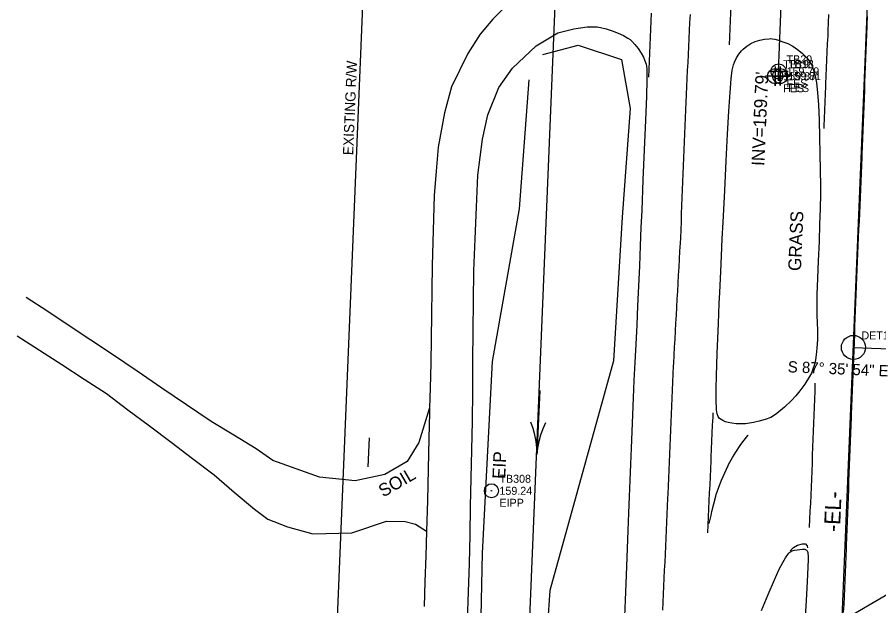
# Model space of a CAD drawing. Extents: x 2262665 to 2270527, y 505476 to 514960.
# Drawn here: x 2266110 to 2266379, y 511484.8 to 511668.5 of the extents above; entities that cross this region are included whole.
import ezdxf

# ---------------------------------------------------------------- set-up
doc = ezdxf.new("R2010")
doc.units = 0
for name, color, linetype in [('Default Symbol Cogo Number', 7, 'Continuous'), ('Exist Horizontal Alignment', 7, 'Continuous'), ('Exist Horizontal Alignment Direction Label', 7, 'Continuous'), ('Exist Hydro River Flow Arrow CELL', 7, 'Continuous'), ('Exist Hydro Stream or Body of Water', 7, 'Continuous'), ('Exist Other Culture Sign', 7, 'Continuous'), ('Exist Property Iron Pin CELL', 7, 'Continuous'), ('Exist Property Iron Pin Cogo Comment', 7, 'Continuous'), ('Exist Property Iron Pin Cogo Elevation', 7, 'Continuous'), ('Exist Property Iron Pin Cogo Number', 7, 'Continuous'), ('Exist Property Iron Pin Text', 7, 'Continuous'), ('Exist Right of Way Control of Access Line', 7, 'Continuous'), ('Exist Right of Way Line', 7, 'Continuous'), ('Exist Right of Way Line Text', 7, 'Continuous'), ('Exist Roads EOP', 7, 'Continuous'), ('Exist Roads EOT', 7, 'Continuous'), ('Exist Roads Soil', 7, 'Continuous'), ('Exist Roads Soil Text', 7, 'Continuous'), ('Exist Structure Minor Paved Ditch or Gutter Cogo Comment', 7, 'Continuous'), ('Exist Structure Minor Paved Ditch or Gutter Cogo Elevation', 7, 'Continuous'), ('Exist Structure Minor Paved Ditch or Gutter Cogo Number', 7, 'Continuous'), ('Exist Structure Minor Paved Ditch or Gutter Cogo Point CELL', 7, 'Continuous'), ('Exist Structure Minor Pipes RCP 15 Inch', 7, 'Continuous'), ('Exist Structure Minor Pipes RCP 15 Inch Cogo Comment', 7, 'Continuous'), ('Exist Structure Minor Pipes RCP 15 Inch Cogo Elevation', 7, 'Continuous'), ('Exist Structure Minor Pipes RCP 15 Inch Cogo Number', 7, 'Continuous'), ('Exist Structure Minor Pipes RCP 15 Inch Cogo Point CELL', 7, 'Continuous'), ('Exist Structure Minor Pipes RCP 15 Inch Invert', 7, 'Continuous'), ('Exist Vegetation Hedge Row Text', 7, 'Continuous')]:
    doc.layers.add(name, color=color, linetype=linetype)

msp = doc.modelspace()

# ---------------------------------------------------------------- linework, layer by layer
at = {"layer": 'Exist Horizontal Alignment'}
for p, q in [((2266320.5, 510340.11), (2266385.32, 511909.14)), ((2266371.12, 511565.48), (2266394.22, 511564.51))]:
    msp.add_line(p, q, dxfattribs=at)
msp.add_circle((2266371.12, 511565.48), 3.75, dxfattribs=at)
at = {"layer": 'Exist Hydro River Flow Arrow CELL'}
msp.add_line((2266272.72, 511542.01), (2266272.72, 511542.01), dxfattribs=at)
msp.add_lwpolyline([(2266275.01, 511541.91), (2266274.14, 511540.05), (2266273.41, 511538.11), (2266272.85, 511536.09), (2266272.45, 511534.06), (2266272.28, 511532.02), (2266273.16, 511552), (2266272.28, 511532.02), (2266272.3, 511534.07), (2266272.08, 511536.13), (2266271.69, 511538.19), (2266271.14, 511540.19), (2266270.44, 511542.11)], dxfattribs=at)
at = {"layer": 'Exist Hydro Stream or Body of Water'}
for points in [[(2266274.13, 511656.9), (2266285.13, 511659.83), (2266298.69, 511655.35), (2266301.39, 511640.07), (2266298.87, 511606.11), (2266296.18, 511561.33), (2266276.32, 511489.55), (2266273.39, 511447.18), (2266269.15, 511402.44), (2266266.62, 511350.29), (2266263.29, 511284.61), (2266261.41, 511233.5)], [(2266242.57, 511233.58), (2266245.62, 511286.27), (2266249.21, 511350.34), (2266253.36, 511402.9), (2266254.17, 511446.9), (2266255.33, 511501.23), (2266258.4, 511561.12), (2266266.85, 511608.7), (2266269.9, 511649.03)]]:
    msp.add_lwpolyline(points, dxfattribs=at)
at = {"layer": 'Exist Other Culture Sign'}
msp.add_line((2266219.93, 511537.26), (2266219.52, 511528.24), dxfattribs=at)
at = {"layer": 'Exist Property Iron Pin CELL'}
for radius in [2.2, 0.0707]:
    msp.add_circle((2266258.09, 511520.72), radius, dxfattribs=at)
at = {"layer": 'Exist Right of Way Control of Access Line'}
msp.add_line((2266232.79, 510577.78), (2266283.35, 511801.46), dxfattribs=at)
at = {"layer": 'Exist Right of Way Line'}
msp.add_line((2266169.17, 510491.24), (2266223.4, 511803.97), dxfattribs=at)
at = {"layer": 'Exist Roads EOP'}
for points in [[(2266263.53, 511672.95), (2266258.49, 511667.96), (2266254.61, 511663.28), (2266250.67, 511657.18), (2266245.65, 511646.8), (2266243.39, 511638.75), (2266241.41, 511628.01), (2266240.83, 511620.47), (2266240.24, 511612.93), (2266240.03, 511605.63), (2266239.82, 511598.33), (2266239.6, 511591.03), (2266239.48, 511583.41), (2266239.36, 511575.79), (2266239.24, 511568.17), (2266239.12, 511560.55), (2266238.92, 511552.76), (2266238.77, 511546.65), (2266238.72, 511544.97), (2266238.52, 511537.18), (2266238.33, 511527.42), (2266238.14, 511517.65), (2266237.84, 511508.13), (2266237.58, 511500.29), (2266237.33, 511492.45), (2266237.08, 511484.6)], [(2266250.58, 511480.2), (2266250.91, 511489.13), (2266251.23, 511498.06), (2266251.41, 511506.94), (2266251.59, 511515.81), (2266251.77, 511524.68), (2266251.95, 511533.55), (2266252.13, 511542.43), (2266252.23, 511551.82), (2266252.33, 511561.22), (2266252.43, 511570.61), (2266252.53, 511580.01), (2266252.63, 511589.41), (2266253.04, 511599.34), (2266253.46, 511609.28), (2266253.87, 511619.22), (2266255.31, 511630.53), (2266256.96, 511638.05), (2266260.43, 511646.66), (2266264.7, 511652.69), (2266272.01, 511659.6), (2266278.87, 511663.67), (2266283.84, 511664.88), (2266287.98, 511665.5), (2266290.81, 511665.58)], [(2266290.81, 511665.58), (2266291.06, 511665.55), (2266292.13, 511665.33), (2266293.89, 511664.89), (2266295.75, 511664.32), (2266297.61, 511663.62), (2266299.28, 511662.86), (2266300.73, 511662.02), (2266301.36, 511661.57), (2266301.92, 511661.1), (2266302.89, 511660.06), (2266303.87, 511658.79), (2266304.85, 511657.34), (2266305.57, 511656.06), (2266306.02, 511654.97), (2266306.37, 511653.85), (2266306.52, 511653.26), (2266306.63, 511652.4), (2266306.66, 511649.15), (2266306.46, 511643.83), (2266306.16, 511636.43), (2266305.78, 511627.2), (2266305.4, 511617.8), (2266305.01, 511608.25), (2266304.79, 511602.93), (2266304.55, 511597.17), (2266304.29, 511590.98), (2266304.02, 511584.64), (2266303.74, 511578.45), (2266303.45, 511572.41), (2266303.15, 511566.52), (2266302.85, 511560.78), (2266302.58, 511555.18), (2266302.33, 511549.72), (2266302.1, 511544.4), (2266301.88, 511539.19), (2266301.68, 511534.05), (2266301.48, 511528.98), (2266301.29, 511523.98), (2266301.1, 511518.93), (2266300.91, 511513.7), (2266300.7, 511508.29), (2266300.47, 511502.7), (2266300.25, 511497.12), (2266300.03, 511491.75), (2266299.83, 511486.58), (2266299.43, 511476.6)], [(2266342.42, 511483.31), (2266344.51, 511488.3), (2266346.45, 511492.93), (2266347.97, 511496.3), (2266349.08, 511498.37), (2266349.94, 511499.84), (2266350.6, 511500.84), (2266350.93, 511501.22), (2266351.27, 511501.53), (2266351.61, 511501.77), (2266351.96, 511501.95), (2266352.32, 511502.09), (2266352.71, 511502.19), (2266353.51, 511502.31), (2266354.36, 511502.4), (2266355.21, 511502.49), (2266355.81, 511502.5), (2266356, 511502.47), (2266356.15, 511502.42), (2266356.3, 511502.34), (2266356.44, 511502.24), (2266356.58, 511502.11), (2266356.7, 511501.95), (2266356.8, 511501.74), (2266356.88, 511501.49), (2266356.93, 511501.19), (2266356.98, 511500.39), (2266356.97, 511499.27), (2266356.87, 511496.93), (2266356.67, 511492.45), (2266356.37, 511486.48), (2266355.99, 511479.65)]]:
    msp.add_lwpolyline(points, dxfattribs=at)
msp.add_lwpolyline([(2266359.86, 511571.16), (2266359.88, 511567.91), (2266359.7, 511565.28), (2266359.45, 511563.21), (2266359.24, 511561.61), (2266358.94, 511560.12), (2266358.39, 511558.37), (2266357.99, 511557.4), (2266357.45, 511556.35), (2266355.95, 511554.05), (2266354.36, 511551.91), (2266353.17, 511550.38), (2266351.77, 511548.87), (2266349.58, 511546.78), (2266347.21, 511544.8), (2266346.2, 511544.12), (2266345.29, 511543.64), (2266343.53, 511542.96), (2266341.65, 511542.41), (2266339.93, 511542.02), (2266338.65, 511541.78), (2266337.46, 511541.65), (2266336, 511541.62), (2266334.51, 511541.67), (2266333.18, 511541.81), (2266332.05, 511542.01), (2266331.15, 511542.25), (2266330.74, 511542.42), (2266330.3, 511542.66), (2266329.32, 511543.33), (2266328.86, 511543.9), (2266328.53, 511544.78), (2266328.34, 511545.97), (2266328.29, 511549.17), (2266328.31, 511552.64), (2266328.36, 511556.64), (2266328.57, 511563.56), (2266328.94, 511572.9), (2266329.2, 511579.22), (2266329.37, 511582.64), (2266329.69, 511589.22), (2266329.92, 511594.07), (2266330.17, 511599.38), (2266330.42, 511604.55), (2266330.92, 511614.5), (2266331.39, 511623.73), (2266331.83, 511632.07), (2266332.24, 511639.26), (2266332.6, 511645.02), (2266332.95, 511649.29), (2266333.3, 511651.98), (2266333.72, 511653.73), (2266333.97, 511654.5), (2266334.59, 511655.84), (2266335.33, 511657.03), (2266335.74, 511657.58), (2266336.19, 511658.1), (2266336.69, 511658.6), (2266337.85, 511659.52), (2266339.13, 511660.31), (2266340.46, 511660.93), (2266341.87, 511661.39), (2266343.4, 511661.69), (2266344.78, 511661.84), (2266345.31, 511661.86), (2266345.72, 511661.83), (2266346.58, 511661.67), (2266347.72, 511661.37), (2266349.07, 511660.92), (2266350.59, 511660.3), (2266352.17, 511659.49), (2266353.69, 511658.47), (2266355.13, 511657.3), (2266356.43, 511656), (2266357, 511655.32), (2266357.5, 511654.64), (2266357.91, 511653.94), (2266358.24, 511653.24), (2266358.77, 511651.76), (2266359.21, 511650.13), (2266359.58, 511648.02), (2266359.91, 511645.05), (2266360.18, 511641.19), (2266360.38, 511636.39), (2266360.53, 511631.14), (2266360.66, 511625.93), (2266360.76, 511620.82), (2266360.8, 511615.88), (2266360.8, 511613.46), (2266360.73, 511608.7), (2266360.58, 511603.93), (2266360.38, 511598.52), (2266360.15, 511592.54), (2266359.92, 511587), (2266359.73, 511582.15), (2266359.66, 511578.48), (2266359.71, 511575.85), (2266359.8, 511572.87)], close=True, dxfattribs=at)
at = {"layer": 'Exist Roads EOT'}
for points in [[(2266332.38, 511659.92), (2266332.49, 511662.42), (2266332.61, 511664.92), (2266332.73, 511667.41), (2266332.85, 511669.91), (2266332.96, 511672.41), (2266333.08, 511674.9), (2266333.2, 511677.4), (2266333.31, 511679.9), (2266333.43, 511682.4), (2266333.55, 511684.89), (2266333.67, 511687.39), (2266333.78, 511689.89), (2266333.85, 511691.33), (2266333.97, 511693.83), (2266334.1, 511696.32), (2266334.22, 511698.82), (2266334.34, 511701.32), (2266334.39, 511702.34)], [(2266307.22, 511649.82), (2266307.33, 511652.32), (2266307.44, 511654.82), (2266307.56, 511657.31), (2266307.67, 511659.81), (2266307.78, 511662.31), (2266307.89, 511664.81), (2266308, 511667.3), (2266308.12, 511669.8)], [(2266311.6, 511483.45), (2266311.72, 511485.95), (2266311.83, 511488.45), (2266311.95, 511490.95), (2266312.06, 511493.44), (2266312.18, 511495.94), (2266312.3, 511498.44), (2266312.41, 511500.94), (2266312.53, 511503.43), (2266312.64, 511505.93), (2266312.76, 511508.43), (2266312.88, 511510.92), (2266312.99, 511513.42), (2266313.11, 511515.92), (2266313.22, 511518.42), (2266313.28, 511519.63), (2266313.39, 511522.13), (2266313.49, 511524.63), (2266313.6, 511527.12), (2266313.7, 511529.62), (2266313.81, 511532.12), (2266313.91, 511534.62), (2266314.02, 511537.12), (2266314.13, 511539.61), (2266314.23, 511542.11), (2266314.34, 511544.61), (2266314.44, 511547.11), (2266314.55, 511549.6), (2266314.66, 511552.1), (2266314.76, 511554.6), (2266314.87, 511557.1), (2266314.97, 511559.6), (2266315.02, 511560.6), (2266315.15, 511563.1), (2266315.29, 511565.59), (2266315.43, 511568.09), (2266315.57, 511570.59), (2266315.71, 511573.08), (2266315.85, 511575.58), (2266315.99, 511578.08), (2266316.13, 511580.57), (2266316.26, 511583.07), (2266316.4, 511585.56), (2266316.54, 511588.06), (2266316.68, 511590.56), (2266316.82, 511593.05), (2266316.96, 511595.55), (2266317.1, 511598.04), (2266317.19, 511599.65), (2266317.29, 511602.15), (2266317.39, 511604.65), (2266317.49, 511607.14), (2266317.59, 511609.64), (2266317.68, 511612.14), (2266317.78, 511614.64), (2266317.88, 511617.14), (2266317.98, 511619.63), (2266318.08, 511622.13), (2266318.18, 511624.63), (2266318.28, 511627.13), (2266318.38, 511629.63), (2266318.48, 511632.12), (2266318.58, 511634.62), (2266318.68, 511637.12), (2266318.78, 511639.62), (2266318.87, 511641.98), (2266318.99, 511644.48), (2266319.12, 511646.97), (2266319.24, 511649.47), (2266319.36, 511651.97), (2266319.48, 511654.46), (2266319.6, 511656.96), (2266319.72, 511659.46), (2266319.84, 511661.95), (2266319.96, 511664.45), (2266320.08, 511666.95), (2266320.2, 511669.45)], [(2266363.32, 511669.36), (2266363.24, 511666.86), (2266363.15, 511664.36), (2266363.09, 511662.75), (2266362.97, 511660.25), (2266362.86, 511657.75), (2266362.75, 511655.25), (2266362.63, 511652.76), (2266362.52, 511650.26), (2266362.4, 511647.76), (2266362.37, 511647.02), (2266362.27, 511644.52), (2266362.17, 511642.02), (2266362.07, 511639.52), (2266361.97, 511637.02), (2266361.87, 511634.53), (2266361.84, 511633.79)], [(2266375.46, 511668.82), (2266375.35, 511666.32), (2266375.32, 511665.7), (2266375.22, 511663.2), (2266375.12, 511660.7), (2266375.02, 511658.21), (2266374.93, 511655.71), (2266374.83, 511653.21), (2266374.73, 511650.71), (2266374.63, 511648.21), (2266374.53, 511645.72), (2266374.44, 511643.22), (2266374.34, 511640.72), (2266374.24, 511638.22), (2266374.14, 511635.72), (2266374.04, 511633.23), (2266373.95, 511630.73), (2266373.85, 511628.23), (2266373.75, 511625.73), (2266373.71, 511624.74), (2266373.61, 511622.24), (2266373.5, 511619.75), (2266373.39, 511617.25), (2266373.29, 511614.75), (2266373.18, 511612.25), (2266373.08, 511609.76), (2266372.97, 511607.26), (2266372.87, 511604.76), (2266372.76, 511602.26), (2266372.65, 511599.76), (2266372.55, 511597.27), (2266372.44, 511594.77), (2266372.34, 511592.27), (2266372.23, 511589.77), (2266372.12, 511587.28), (2266372.02, 511584.78), (2266372.01, 511584.49), (2266371.91, 511582), (2266371.81, 511579.5), (2266371.71, 511577), (2266371.61, 511574.5), (2266371.51, 511572), (2266371.41, 511569.51), (2266371.31, 511567.01), (2266371.21, 511564.51), (2266371.11, 511562.01), (2266371.01, 511559.51), (2266370.91, 511557.02), (2266370.81, 511554.52), (2266370.71, 511552.02), (2266370.61, 511549.52), (2266370.51, 511547.02), (2266370.41, 511544.53), (2266370.38, 511543.62), (2266370.29, 511541.13), (2266370.19, 511538.63), (2266370.1, 511536.13), (2266370.01, 511533.63), (2266369.91, 511531.13), (2266369.82, 511528.63), (2266369.73, 511526.14), (2266369.63, 511523.64), (2266369.54, 511521.14), (2266369.45, 511518.64), (2266369.35, 511516.14), (2266369.26, 511513.65), (2266369.17, 511511.15), (2266369.08, 511508.65), (2266368.98, 511506.15), (2266368.89, 511503.65), (2266368.85, 511502.7), (2266368.74, 511500.2), (2266368.63, 511497.71), (2266368.52, 511495.21), (2266368.41, 511492.71), (2266368.3, 511490.21), (2266368.19, 511487.72), (2266368.08, 511485.22), (2266367.97, 511482.72)], [(2266359.12, 511554.35), (2266359.03, 511551.85), (2266358.94, 511549.35), (2266358.85, 511546.86), (2266358.76, 511544.36), (2266358.66, 511541.86), (2266358.57, 511539.36), (2266358.48, 511536.86), (2266358.39, 511534.36), (2266358.29, 511531.87), (2266358.2, 511529.37), (2266358.11, 511526.87), (2266358.02, 511524.37), (2266357.9, 511521.87), (2266357.78, 511519.38), (2266357.67, 511516.88), (2266357.55, 511514.38), (2266357.43, 511511.88), (2266357.31, 511509.39), (2266357.31, 511509.24)], [(2266325.69, 511507.59), (2266325.8, 511510.09), (2266325.9, 511512.58), (2266326.01, 511515.08), (2266326.12, 511517.58), (2266326.23, 511520.08), (2266326.34, 511522.57), (2266326.45, 511525.07), (2266326.55, 511527.57), (2266326.66, 511530.07), (2266326.71, 511531.2), (2266326.83, 511533.7), (2266326.94, 511536.2), (2266327.05, 511538.69), (2266327.17, 511541.19), (2266327.28, 511543.69), (2266327.35, 511545.09)], [(2266326.12, 511510.54), (2266326.66, 511512.98), (2266326.93, 511514.21), (2266327.54, 511516.64), (2266328.15, 511519.06), (2266328.28, 511519.56), (2266329.14, 511521.9), (2266329.92, 511524.02), (2266330.94, 511526.3), (2266331.96, 511528.58), (2266332.13, 511528.97), (2266333.4, 511531.12), (2266334.38, 511532.77), (2266335.8, 511534.83), (2266336.6, 511535.98), (2266338.14, 511537.95), (2266338.27, 511538.12)], [(2266351.4, 511501.97), (2266352.37, 511503.02), (2266353.64, 511503.72), (2266355.19, 511504.17), (2266356.17, 511504.13), (2266356.69, 511503.55), (2266356.78, 511502.91)]]:
    msp.add_lwpolyline(points, dxfattribs=at)
at = {"layer": 'Exist Roads Soil'}
for points in [[(2266238.77, 511546.65), (2266235.46, 511535.8), (2266231.79, 511529.9), (2266224.82, 511525.84), (2266215.57, 511523.86), (2266204.37, 511524.96), (2266197.12, 511527.57), (2266189.88, 511530.18), (2266184.65, 511533.86), (2266177.61, 511538.08), (2266170.58, 511542.3), (2266162.87, 511547.55), (2266155.15, 511552.8), (2266147.44, 511558.05), (2266139.72, 511563.29), (2266132.99, 511567.75), (2266126.26, 511572.2), (2266119.53, 511576.66), (2266112.8, 511581.11)], [(2266110.01, 511569.09), (2266116.98, 511564.6), (2266123.94, 511560.1), (2266130.9, 511555.61), (2266137.86, 511551.11), (2266144.59, 511546.03), (2266151.31, 511540.95), (2266158.04, 511535.87), (2266164.76, 511530.78), (2266171.49, 511525.7), (2266177.79, 511520.33), (2266184.1, 511514.96), (2266188.31, 511511.91), (2266194.36, 511509.42), (2266202.32, 511507.25), (2266214.49, 511507.6), (2266225.35, 511511.22), (2266231.19, 511511.16), (2266234.37, 511510.33), (2266237.84, 511508.13)]]:
    msp.add_lwpolyline(points, dxfattribs=at)
at = {"layer": 'Exist Structure Minor Paved Ditch or Gutter Cogo Point CELL'}
for points in [[(2266346.7, 511653.13), (2266346.7, 511647.13), (2266346.7, 511650.13), (2266349.7, 511650.13), (2266343.7, 511650.13)], [(2266348.27, 511653.19), (2266348.27, 511647.19), (2266348.27, 511650.19), (2266351.27, 511650.19), (2266345.27, 511650.19)]]:
    msp.add_lwpolyline(points, dxfattribs=at)
for centre in [(2266346.7, 511650.13), (2266348.27, 511650.19)]:
    msp.add_circle(centre, 2.34, dxfattribs=at)
at = {"layer": 'Exist Structure Minor Pipes RCP 15 Inch'}
for p, q in [((2266347.74, 511651.65), (2266350.05, 511708.04)), ((2266410.81, 511505.33), (2266345.76, 511467.41))]:
    msp.add_line(p, q, dxfattribs=at)
at = {"layer": 'Exist Structure Minor Pipes RCP 15 Inch Cogo Point CELL'}
msp.add_lwpolyline([(2266347.74, 511654.65), (2266347.74, 511648.65), (2266347.74, 511651.65), (2266350.74, 511651.65), (2266344.74, 511651.65)], dxfattribs=at)
msp.add_circle((2266347.74, 511651.65), 2.34, dxfattribs=at)

# ---------------------------------------------------------------- texts
at = {"layer": 'Default Symbol Cogo Number'}
msp.add_text('DET114', height=2.5, dxfattribs=at).set_placement((2266373.62, 511567.98))
at = {"layer": 'Exist Horizontal Alignment Direction Label'}
for s, height, rotation, p in [('S 87%%d 35\' 54" E', 3.5, 357.5983, (2266350.57, 511557.72)), ('-EL-', 5, 87.5983, (2266366.91, 511507.79))]:
    msp.add_text(s, height=height, rotation=rotation, dxfattribs=at).set_placement(p)
at = {"layer": 'Exist Property Iron Pin Cogo Comment'}
msp.add_text('EIPP', height=2.5, dxfattribs=at).set_placement((2266260.59, 511515.72))
at = {"layer": 'Exist Property Iron Pin Cogo Elevation'}
msp.add_text('159.24', height=2.5, dxfattribs=at).set_placement((2266260.59, 511519.47))
at = {"layer": 'Exist Property Iron Pin Cogo Number'}
msp.add_text('TB308', height=2.5, dxfattribs=at).set_placement((2266260.59, 511523.22))
at = {"layer": 'Exist Property Iron Pin Text'}
msp.add_text('EIP', height=4, rotation=87.4803, dxfattribs=at).set_placement((2266262.37, 511524.33))
at = {"layer": 'Exist Right of Way Line Text'}
msp.add_text('EXISTING R/W', height=3.2, rotation=87.5983, dxfattribs=at).set_placement((2266214.9, 511625.43))
at = {"layer": 'Exist Roads Soil Text'}
msp.add_text('SOIL', height=4, rotation=30.2102, dxfattribs=at).set_placement((2266224.31, 511518.59))
at = {"layer": 'Exist Structure Minor Paved Ditch or Gutter Cogo Comment'}
for p in [(2266349.2, 511645.13), (2266350.77, 511645.19)]:
    msp.add_text('FES', height=2.5, dxfattribs=at).set_placement(p)
at = {"layer": 'Exist Structure Minor Paved Ditch or Gutter Cogo Elevation'}
for s, p in [('159.87', (2266349.2, 511648.88)), ('159.81', (2266350.77, 511648.94))]:
    msp.add_text(s, height=2.5, dxfattribs=at).set_placement(p)
at = {"layer": 'Exist Structure Minor Paved Ditch or Gutter Cogo Number'}
for s, p in [('TB19', (2266349.2, 511652.63)), ('TB18', (2266350.77, 511652.69))]:
    msp.add_text(s, height=2.5, dxfattribs=at).set_placement(p)
at = {"layer": 'Exist Structure Minor Pipes RCP 15 Inch Cogo Comment'}
msp.add_text('FES', height=2.5, dxfattribs=at).set_placement((2266350.24, 511646.65))
at = {"layer": 'Exist Structure Minor Pipes RCP 15 Inch Cogo Elevation'}
msp.add_text('159.79', height=2.5, dxfattribs=at).set_placement((2266350.24, 511650.4))
at = {"layer": 'Exist Structure Minor Pipes RCP 15 Inch Cogo Number'}
msp.add_text('TB20', height=2.5, dxfattribs=at).set_placement((2266350.24, 511654.15))
at = {"layer": 'Exist Structure Minor Pipes RCP 15 Inch Invert'}
msp.add_text("INV=159.79'", height=4, rotation=87.4803, dxfattribs=at).set_placement((2266343.29, 511622.06))
at = {"layer": 'Exist Vegetation Hedge Row Text'}
msp.add_text('GRASS', height=4, rotation=87.5804, dxfattribs=at).set_placement((2266354.73, 511589.27))

doc.saveas('drawing.dxf')
